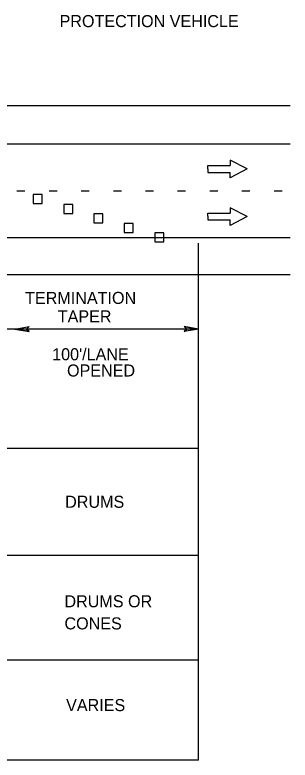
# Model space of a CAD drawing. Extents: x 12.4 to 19.6, y 4 to 16.
# Drawn here: x 18.132 to 19.502, y 8.348 to 12.055 of the extents above; entities that cross this region are included whole.
import ezdxf

# ---------------------------------------------------------------- set-up
doc = ezdxf.new("R2010")
doc.units = 0
for name, color, linetype in [('DETL-DIMS', 7, 'Continuous'), ('DETL-LINE', 7, 'Continuous'), ('DETL-NOTE', 7, 'Continuous'), ('MRKG-LINE', 7, 'Continuous'), ('USER-BORD', 7, 'Continuous')]:
    doc.layers.add(name, color=color, linetype=linetype)

# ---------------------------------------------------------------- blocks, each defined once
blk = doc.blocks.new('DIR2')
at = {"layer": 'USER-BORD'}
for p, q in [((0, 0.001), (-0.034, -0.048)), ((0, 0.001), (0.034, -0.048)), ((-0.034, -0.048), (-0.013, -0.048)), ((-0.013, -0.113), (-0.013, -0.048)), ((0.034, -0.048), (0.013, -0.048)), ((0.013, -0.113), (0.013, -0.048)), ((-0.001, -0.113), (-0.013, -0.113)), ((-0.001, -0.113), (0.001, -0.113)), ((0.001, -0.113), (0.013, -0.113))]:
    blk.add_line(p, q, dxfattribs=at)

msp = doc.modelspace()

# ---------------------------------------------------------------- linework, layer by layer
at = {"layer": 'DETL-DIMS'}
for p, q in [((19.0458, 8.348), (19.0458, 10.9192)), ((19.0458, 10.4922), (13.3764, 10.4922)), ((18.1322, 10.4922), (18.2037, 10.5048)), ((18.1322, 10.4922), (18.2037, 10.4796)), ((18.1902, 10.4922), (18.2037, 10.5048)), ((18.2037, 10.4796), (18.1902, 10.4922)), ((19.0458, 10.4922), (18.9743, 10.5048)), ((18.9743, 10.5048), (18.9878, 10.4922)), ((19.0458, 10.4922), (18.9743, 10.4796)), ((18.9878, 10.4922), (18.9743, 10.4796)), ((19.0458, 9.8978), (12.4073, 9.8978)), ((19.0458, 9.3657), (12.4073, 9.3657)), ((19.0458, 8.8452), (12.4073, 8.8452)), ((19.0458, 8.348), (12.4073, 8.348))]:
    msp.add_line(p, q, dxfattribs=at)
for points in [[(18.2037, 10.4796), (18.1322, 10.4922), (18.2037, 10.5048), (18.1902, 10.4922)], [(18.9743, 10.5048), (19.0458, 10.4922), (18.9743, 10.4796), (18.9878, 10.4922)]]:
    msp.add_lwpolyline(points, close=True, dxfattribs=at)
at = {"layer": 'MRKG-LINE'}
for p, q in [((19.5024, 11.6019), (12.7024, 11.6019)), ((19.5024, 11.411), (12.7024, 11.411)), ((18.1824, 11.1781), (18.1424, 11.1781)), ((18.1824, 11.1781), (18.1424, 11.1781)), ((18.1824, 11.1781), (18.1424, 11.1781)), ((18.3424, 11.1781), (18.3024, 11.1781)), ((18.5024, 11.1781), (18.4624, 11.1781)), ((18.6624, 11.1781), (18.6224, 11.1781)), ((18.8224, 11.1781), (18.7824, 11.1781)), ((18.9824, 11.1781), (18.9424, 11.1781)), ((19.1424, 11.1781), (19.1024, 11.1781)), ((19.3024, 11.1781), (19.2624, 11.1781)), ((19.4624, 11.1781), (19.4224, 11.1781)), ((19.5024, 10.9461), (12.7024, 10.9461)), ((19.5024, 10.7623), (12.7024, 10.7623))]:
    msp.add_line(p, q, dxfattribs=at)
for points in [[(18.2233, 11.1618), (18.2233, 11.117), (18.2681, 11.117), (18.2681, 11.1618)], [(18.3751, 11.111), (18.3751, 11.0662), (18.4199, 11.0662), (18.4199, 11.111)], [(18.5255, 11.0644), (18.5255, 11.0196), (18.5703, 11.0196), (18.5703, 11.0644)], [(18.6759, 11.0164), (18.6759, 10.9716), (18.7207, 10.9716), (18.7207, 11.0164)], [(18.8283, 10.9712), (18.8283, 10.9264), (18.8731, 10.9264), (18.8731, 10.9712)]]:
    msp.add_lwpolyline(points, close=True, dxfattribs=at)

# ---------------------------------------------------------------- block references
at = {"layer": 'DETL-LINE', "xscale": 1.2917647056, "yscale": 1.7223529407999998, "rotation": -90.00000000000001}
for p in [(19.2866, 11.2882), (19.2866, 11.0515)]:
    msp.add_blockref('DIR2', p, dxfattribs=at)

# ---------------------------------------------------------------- texts
at = {"layer": 'DETL-NOTE'}
for s, p in [('PROTECTION VEHICLE ', (18.3547, 11.9936)), ('DRUMS ', (18.3825, 9.6028)), ('DRUMS OR ', (18.379, 9.108)), ('CONES', (18.379, 8.998))]:
    msp.add_text(s, height=0.06, dxfattribs=at).set_placement(p)
for s, p in [('TERMINATION', (18.1832, 10.6169)), ('TAPER', (18.3457, 10.525)), ("100'/LANE", (18.3178, 10.3366)), ('OPENED', (18.3918, 10.2559)), ('VARIES', (18.3872, 8.5916))]:
    msp.add_text(s, height=0.06, rotation=360, dxfattribs=at).set_placement(p)

doc.saveas('drawing.dxf')
